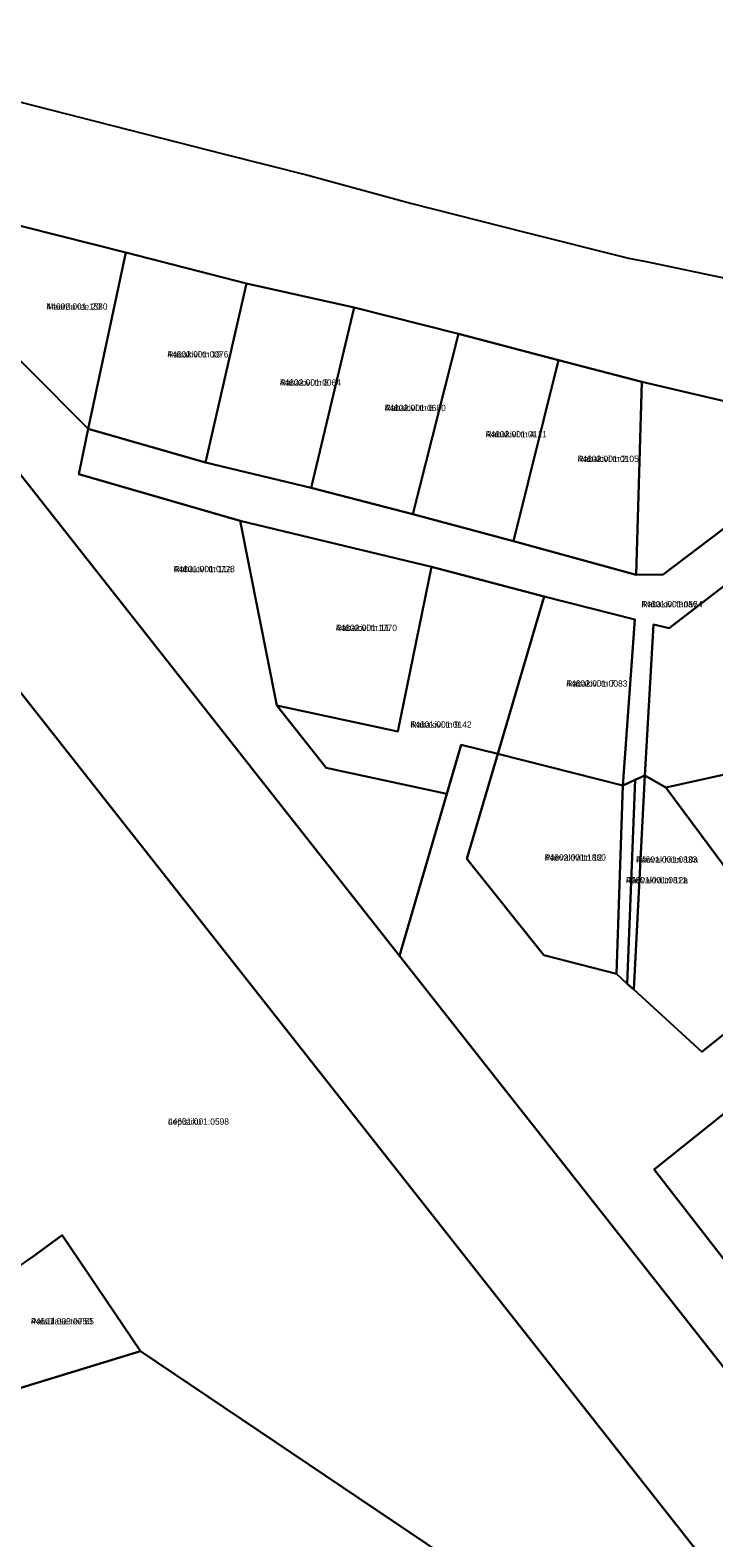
# Model space of a CAD drawing. Extents: x 551843 to 558501, y 6589003 to 6595718.
# Drawn here: x 553892.5 to 554054.7, y 6593798.2 to 6594156.3 of the extents above; entities that cross this region are included whole.
import ezdxf

# ---------------------------------------------------------------- set-up
doc = ezdxf.new("R2010")
doc.units = 0
for name, color, linetype in [('L_AADRESS', 7, 'Continuous'), ('PIIR', 7, 'Continuous'), ('TUNNUS', 7, 'Continuous')]:
    doc.layers.add(name, color=color, linetype=linetype)

msp = doc.modelspace()

# ---------------------------------------------------------------- linework, layer by layer
at = {"layer": 'PIIR'}
for points in [[(554441.09, 6593299.31), (554261.19, 6593527.78), (554141.98, 6593679.18), (554122.61, 6593703.78), (554013.74, 6593842.05), (553788.87, 6594127.63), (553766.28, 6594156.32), (553814.68, 6594146.58), (553836.64, 6594118.69), (553980.12, 6593936.47), (554062.14, 6593832.31), (554258.75, 6593582.61), (554309.59, 6593518.04), (554467.93, 6593316.95)], [(553889.7, 6594139.37), (553938.59, 6594126.9), (553958.38, 6594121.91), (553982.77, 6594115.26), (554009.89, 6594108.34), (554034.49, 6594102.2), (554038.7, 6594101.39), (554090.15, 6594090.55), (554113.86, 6594085.56), (554150.52, 6594077.85), (554179.61, 6594071.61), (554187.54, 6594069.56), (554206.48, 6594065.55), (554227.04, 6594061.58), (554247.41, 6594057.1), (554247.36, 6594055.59), (554255.55, 6594050.77), (554270.86, 6594048.2), (554286.8, 6594045.65), (554325.88, 6594037.38), (554348.01, 6594032.83), (554370.34, 6594028.21), (554392.77, 6594023.55)], [(553788.87, 6594127.63), (554013.74, 6593842.05), (554122.61, 6593703.78)], [(554380.71, 6593995.18), (554355.1, 6594001.3), (554331.32, 6594005.86), (554306.78, 6594010.82), (554282.1, 6594015.75), (554258.26, 6594020.72), (554244.12, 6594023.25), (554236.44, 6594024.63), (554212.91, 6594029.17), (554189.31, 6594034.64), (554149.15, 6594042.88), (554111.26, 6594058), (554100.91, 6594057.97), (554087.64, 6594061.09), (554037.7, 6594072.82), (554017.88, 6594077.9), (553994.12, 6594084.15), (553969.4, 6594090.48), (553943.83, 6594096.11), (553915.21, 6594103.47), (553883.5, 6594111.54)], [(554062.14, 6593832.31), (553980.12, 6593936.47), (553991.37, 6593974.95), (553994.76, 6593986.55), (554003.5, 6593984.44), (553996.11, 6593959.5), (554014.39, 6593936.59), (554031.68, 6593932.21), (554034.21, 6593929.82), (554035.77, 6593928.42), (554051.94, 6593913.62), (554075.81, 6593932.73)], [(554046.25, 6593756.59), (553918.7, 6593842.58), (553900.13, 6593870.11), (553892.97, 6593864.88), (553892.29, 6593864.39)], [(553758.61, 6593795.24), (553769.62, 6593798.93), (553797.08, 6593806.79), (553818.66, 6593812.78), (553858.07, 6593824.49), (553870.08, 6593827.69), (553909.89, 6593839.88), (553918.7, 6593842.58), (554046.25, 6593756.59)]]:
    msp.add_lwpolyline(points, dxfattribs=at)
for points in [[(553991.37, 6593974.95), (553980.12, 6593936.47), (553836.64, 6594118.69), (553883.5, 6594111.54), (553877.52, 6594090.46), (553906.3, 6594061.6), (553904.05, 6594050.84), (553942.36, 6594039.81), (553951.03, 6593995.91), (553962.77, 6593981.08)], [(553915.21, 6594103.47), (553906.3, 6594061.6), (553877.52, 6594090.46), (553883.5, 6594111.54)], [(553915.21, 6594103.47), (553943.83, 6594096.11), (553934.12, 6594053.6), (553906.3, 6594061.6)], [(553934.12, 6594053.6), (553943.83, 6594096.11), (553969.4, 6594090.48), (553959.18, 6594047.59)], [(553994.12, 6594084.15), (553983.33, 6594041.32), (553959.18, 6594047.59), (553969.4, 6594090.48)], [(553983.33, 6594041.32), (553994.12, 6594084.15), (554017.88, 6594077.9), (554007.18, 6594034.98)], [(554017.88, 6594077.9), (554037.7, 6594072.82), (554036.32, 6594026.94), (554007.18, 6594034.98)], [(554042.71, 6594027.01), (554036.32, 6594026.94), (554037.7, 6594072.82), (554087.64, 6594061.09)], [(553906.3, 6594061.6), (553934.12, 6594053.6), (553959.18, 6594047.59), (553983.33, 6594041.32), (554007.18, 6594034.98), (554036.32, 6594026.94), (554042.71, 6594027.01), (554087.64, 6594061.09), (554100.91, 6594057.97), (554084.31, 6594045.38), (554064.37, 6594029.85), (554044.16, 6594014.26), (554040.4, 6594015.17), (554038.41, 6593979.28), (554036.1, 6593978.22), (554033.15, 6593976.89), (554035.98, 6594016.31), (554014.49, 6594021.82), (553987.74, 6594028.85), (553942.36, 6594039.81), (553904.05, 6594050.84)], [(553951.03, 6593995.91), (553942.36, 6594039.81), (553987.74, 6594028.85), (553979.75, 6593989.74)], [(554044.16, 6594014.26), (554064.37, 6594029.85), (554089.53, 6593997.69), (554069.13, 6593982.12), (554043.35, 6593976.47), (554038.41, 6593979.28), (554040.4, 6594015.17)], [(553979.75, 6593989.74), (553987.74, 6594028.85), (554014.49, 6594021.82), (554003.5, 6593984.44), (553994.76, 6593986.55), (553991.37, 6593974.95), (553962.77, 6593981.08), (553951.03, 6593995.91)], [(554014.49, 6594021.82), (554035.98, 6594016.31), (554033.15, 6593976.89), (554003.5, 6593984.44)], [(553996.11, 6593959.5), (554003.5, 6593984.44), (554033.15, 6593976.89), (554031.68, 6593932.21), (554014.39, 6593936.59)], [(554191.55, 6593952.2), (554166.53, 6593985.52), (554143.91, 6593967.95), (554123.29, 6593951.6), (554102.17, 6593934.89), (554081.29, 6593918.18), (554061.66, 6593902.58), (554040.61, 6593885.71), (554064.46, 6593854.9), (554089.96, 6593822.55), (554109.26, 6593837.8), (554131.23, 6593854.91), (554152.21, 6593871.22), (554172.64, 6593886.37), (554194.81, 6593902.57), (554216.24, 6593918.63)], [(554043.35, 6593976.47), (554069.13, 6593982.12), (554096.57, 6593949.41), (554075.81, 6593932.73)], [(554031.68, 6593932.21), (554033.15, 6593976.89), (554036.1, 6593978.22), (554034.21, 6593929.82)], [(554034.21, 6593929.82), (554036.1, 6593978.22), (554038.41, 6593979.28), (554035.77, 6593928.42)], [(554043.35, 6593976.47), (554075.81, 6593932.73), (554051.94, 6593913.62), (554035.77, 6593928.42), (554038.41, 6593979.28)], [(554061.66, 6593902.58), (554085, 6593870.6), (554064.46, 6593854.9), (554040.61, 6593885.71)], [(553870.08, 6593827.69), (553860.87, 6593841.59), (553892.29, 6593864.39), (553892.97, 6593864.88), (553900.13, 6593870.11), (553918.7, 6593842.58), (553909.89, 6593839.88)]]:
    msp.add_lwpolyline(points, close=True, dxfattribs=at)

# ---------------------------------------------------------------- texts
at = {"layer": 'L_AADRESS'}
for s, p in [('Maardu tee 20', (553896.37, 6594089.91)), ('Rabakivi tn 10', (553925.06, 6594078.57)), ('Rabakivi tn 8', (553951.76, 6594071.87)), ('Rabakivi tn 6', (553976.65, 6594065.84)), ('Rabakivi tn 4', (554000.61, 6594059.59)), ('Rabakivi tn 2', (554022.44, 6594053.75)), ('Rabakivi tn 11a', (553926.58, 6594027.58)), ('Rabakivi tänav', (554037.58, 6594019.25)), ('Rabakivi tn 11', (553965.05, 6594013.61)), ('Rabakivi tn 7', (554019.74, 6594000.39)), ('Rabakivi tn 9', (553982.76, 6593990.63)), ('Päevakivi tn 12', (554014.63, 6593959.07)), ('Päevakivi tn 10a', (554036.31, 6593958.57)), ('Päevakivi tn 12a', (554033.89, 6593953.67)), ('Lepistiku', (553925.2, 6593896.34)), ('Paluülase tee 65', (553892.69, 6593848.9))]:
    msp.add_text(s, height=1.5, dxfattribs=at).set_placement(p)
at = {"layer": 'TUNNUS'}
for s, p in [('44602:001:1580', (553896.37, 6594089.91)), ('44602:001:0076', (553925.06, 6594078.57)), ('44602:001:0064', (553951.76, 6594071.87)), ('44602:001:0680', (553976.65, 6594065.84)), ('44602:001:0111', (554000.61, 6594059.59)), ('44602:001:0105', (554022.44, 6594053.75)), ('44601:001:0778', (553926.58, 6594027.58)), ('44601:001:0554', (554037.58, 6594019.25)), ('44602:001:1770', (553965.05, 6594013.61)), ('44602:001:0083', (554019.74, 6594000.39)), ('44601:001:0142', (553982.76, 6593990.63)), ('44602:001:1860', (554014.63, 6593959.07)), ('44601:001:0833', (554036.31, 6593958.57)), ('44601:001:0811', (554033.89, 6593953.67)), ('44601:001:0598', (553925.2, 6593896.34)), ('44601:003:0750', (553892.69, 6593848.9))]:
    msp.add_text(s, height=1.5, dxfattribs=at).set_placement(p)

doc.saveas('drawing.dxf')
